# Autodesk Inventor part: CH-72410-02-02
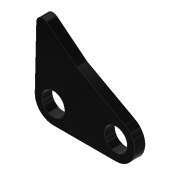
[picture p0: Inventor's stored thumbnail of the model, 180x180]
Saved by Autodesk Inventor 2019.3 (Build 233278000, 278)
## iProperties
Created: 2012-10
Part Number: CH-72410-02-02
Material: Ogólny
Document SubType Name: Modeling
Designer: CADENGINEERING4
Density: 1 g/cm^3
Appearance: Gładki — czarny
Author: CADENGINEERING4
Revision Number: ÈÎºÎ
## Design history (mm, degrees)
feature "Í¹Ì¨-À­Éì1"
node "Bryła1"
